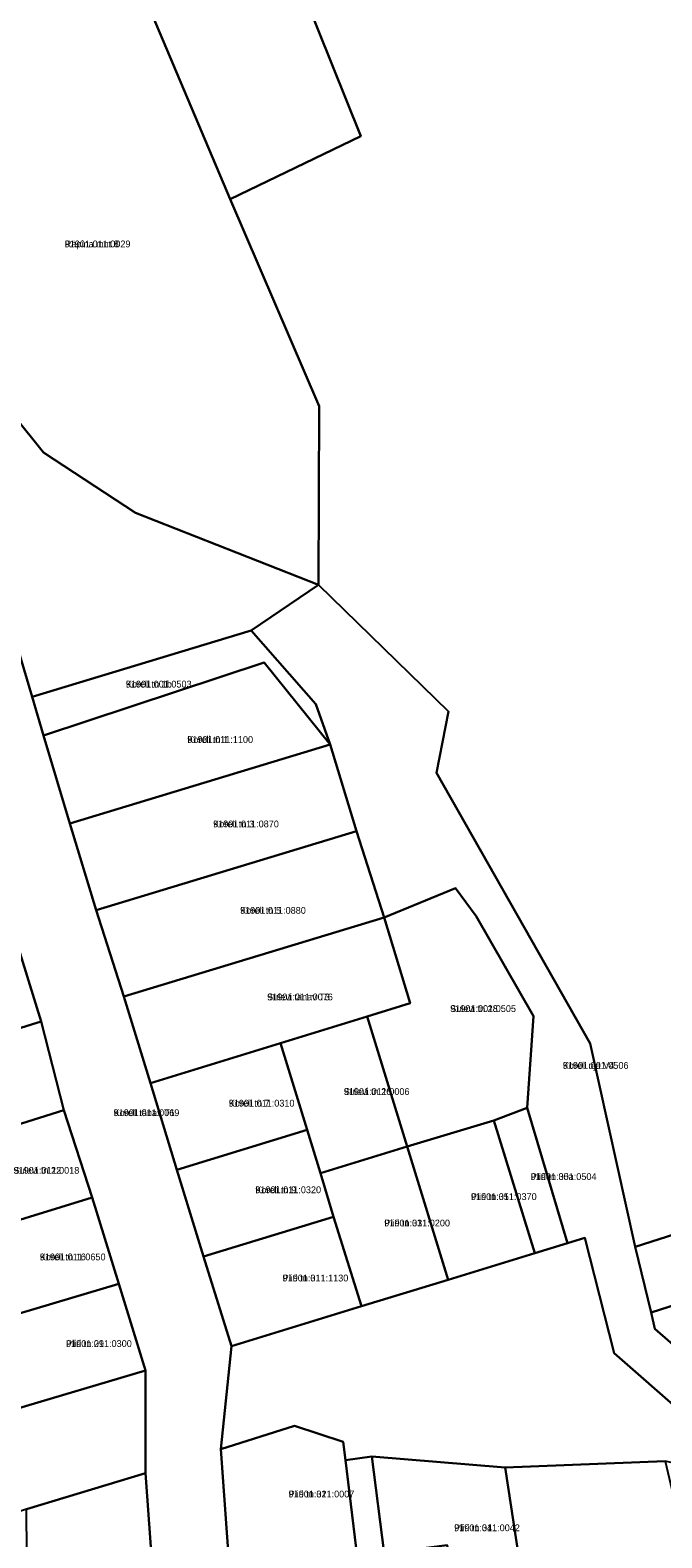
# Model space of a CAD drawing. Extents: x 675810 to 681273, y 6411190 to 6417565.
# Drawn here: x 678927.8 to 679067.1, y 6414897.2 to 6415229.9 of the extents above; entities that cross this region are included whole.
import ezdxf

# ---------------------------------------------------------------- set-up
doc = ezdxf.new("R2010")
doc.units = 0
for name, color, linetype in [('L_AADRESS', 7, 'Continuous'), ('PIIR', 7, 'Continuous'), ('TUNNUS', 7, 'Continuous')]:
    doc.layers.add(name, color=color, linetype=linetype)

msp = doc.modelspace()

# ---------------------------------------------------------------- linework, layer by layer
at = {"layer": 'PIIR'}
for points in [[(679238.99, 6415018.2), (679061.22, 6414961.43), (679051.32, 6415006.26), (679017.45, 6415066.02), (679020.06, 6415079.54), (678991.43, 6415107.45), (678991.54, 6415146.92), (678971.88, 6415192.56), (679000.73, 6415206.48), (678975.31, 6415269.85), (679026.21, 6415288.48), (679036.29, 6415260.94), (679042.8, 6415263.32), (679133.21, 6415296.47)], [(678907.99, 6415150.83), (678928.23, 6415082.74), (678930.76, 6415074.23), (678936.53, 6415054.84), (678942.34, 6415035.68), (678948.45, 6415016.65), (678954.32, 6414997.52), (678960.17, 6414978.4), (678966.04, 6414959.29), (678972.21, 6414939.48), (678969.88, 6414916.74), (678972, 6414887.15)], [(679072, 6414924.49), (679056.59, 6414937.95), (679050.17, 6414963.38), (679046.33, 6414962.2), (679037.43, 6414992.05), (679038.79, 6415012.34), (679026.19, 6415034.35), (679021.61, 6415040.53), (679005.86, 6415034.08), (678999.75, 6415053.14), (678993.95, 6415072.26), (678990.84, 6415081.16), (678976.51, 6415097.38), (678991.43, 6415107.45), (679020.06, 6415079.54), (679017.45, 6415066.02), (679051.32, 6415006.26), (679061.22, 6414961.43), (679064.74, 6414946.94), (679065.6, 6414943.33), (679076.56, 6414933.76)], [(678956.03, 6414872.89), (678953.21, 6414911.44), (678953.22, 6414934.12), (678947.33, 6414953.22), (678941.44, 6414972.33), (678935.25, 6414991.58), (678930.22, 6415011.1), (678924.33, 6415030.21)], [(679145.84, 6414896.58), (679067.84, 6414914.13), (679032.54, 6414912.69), (679003.18, 6414915.16), (678997.34, 6414914.37), (678996.85, 6414918.42), (678986.12, 6414921.92), (678969.88, 6414916.74), (678972.21, 6414939.48), (679000.89, 6414948.31), (679019.98, 6414954.16), (679039.1, 6414960.02), (679046.33, 6414962.2), (679050.17, 6414963.38), (679056.59, 6414937.95), (679072, 6414924.49), (679167.39, 6414906.13), (679297.57, 6414893.92), (679335.8, 6414897.92), (679339.92, 6414883.16)]]:
    msp.add_lwpolyline(points, dxfattribs=at)
for points in [[(678944.73, 6415258.64), (678975.31, 6415269.85), (679000.73, 6415206.48), (678971.88, 6415192.56), (678953.18, 6415237.02), (678947.08, 6415252.89)], [(678938.21, 6415256.44), (678940.28, 6415250.38), (678947.08, 6415252.89), (678953.18, 6415237.02), (678971.88, 6415192.56), (678991.54, 6415146.92), (678991.43, 6415107.45), (678951.01, 6415123.4), (678930.74, 6415136.65), (678883.06, 6415196.06), (678814.45, 6415217.97), (678811.5, 6415229.05), (678924.62, 6415251.82)], [(678811.5, 6415229.05), (678814.45, 6415217.97), (678883.06, 6415196.06), (678930.74, 6415136.65), (678951.01, 6415123.4), (678991.43, 6415107.45), (678976.51, 6415097.38), (678928.23, 6415082.74), (678907.99, 6415150.83), (678896.81, 6415163.44), (678866.24, 6415192.19), (678833.97, 6415200.67), (678806.69, 6415206.19), (678789.69, 6415215.27), (678785.99, 6415219.46), (678784.18, 6415224.88)], [(678930.76, 6415074.23), (678928.23, 6415082.74), (678976.51, 6415097.38), (678990.84, 6415081.16), (678993.95, 6415072.26), (678979.43, 6415090.36)], [(678936.53, 6415054.84), (678930.76, 6415074.23), (678979.43, 6415090.36), (678993.95, 6415072.26)], [(678999.75, 6415053.14), (678942.34, 6415035.68), (678936.53, 6415054.84), (678993.95, 6415072.26)], [(678999.75, 6415053.14), (679005.86, 6415034.08), (678948.45, 6415016.65), (678942.34, 6415035.68)], [(679005.86, 6415034.08), (679021.61, 6415040.53), (679026.19, 6415034.35), (679038.79, 6415012.34), (679037.43, 6414992.05), (679030.1, 6414989.29), (679010.94, 6414983.54), (679002.12, 6415012.21), (679011.6, 6415015.17)], [(678948.45, 6415016.65), (679005.86, 6415034.08), (679011.6, 6415015.17), (679002.12, 6415012.21), (678983, 6415006.33), (678954.32, 6414997.52)], [(678895.65, 6415021.37), (678924.33, 6415030.21), (678930.22, 6415011.1), (678901.53, 6415002.27)], [(679244.09, 6415004.39), (679064.74, 6414946.94), (679061.22, 6414961.43), (679238.99, 6415018.2)], [(678777.48, 6414963.9), (678805.96, 6414972.84), (678825.07, 6414978.72), (678844.19, 6414984.61), (678863.31, 6414990.49), (678882.46, 6414996.39), (678901.53, 6415002.27), (678930.22, 6415011.1), (678935.25, 6414991.58), (678906.93, 6414982.64), (678887.82, 6414976.76), (678868.7, 6414970.88), (678849.58, 6414965), (678830.47, 6414959.11), (678811.35, 6414953.21), (678782.68, 6414944.38)], [(679010.94, 6414983.54), (678991.83, 6414977.66), (678988.88, 6414987.22), (678983, 6415006.33), (679002.12, 6415012.21)], [(679076.56, 6414933.76), (679065.6, 6414943.33), (679064.74, 6414946.94), (679244.09, 6415004.39), (679255.75, 6415008.13), (679263.5, 6414986.2), (679272.89, 6414959.53), (679314.4, 6414967.13), (679333.36, 6414907.74), (679297.53, 6414903.93), (679168.83, 6414916.01)], [(678954.32, 6414997.52), (678983, 6415006.33), (678988.88, 6414987.22), (678960.17, 6414978.4)], [(678906.93, 6414982.64), (678935.25, 6414991.58), (678941.44, 6414972.33), (678912.78, 6414963.51)], [(679030.1, 6414989.29), (679037.43, 6414992.05), (679046.33, 6414962.2), (679039.1, 6414960.02)], [(679019.98, 6414954.16), (679010.94, 6414983.54), (679030.1, 6414989.29), (679039.1, 6414960.02)], [(678960.17, 6414978.4), (678988.88, 6414987.22), (678991.83, 6414977.66), (678994.73, 6414968.07), (678966.04, 6414959.29)], [(679000.89, 6414948.31), (678994.73, 6414968.07), (678991.83, 6414977.66), (679010.94, 6414983.54), (679019.98, 6414954.16)], [(678918.19, 6414944.55), (678915.25, 6414954.11), (678912.78, 6414963.51), (678941.44, 6414972.33), (678947.33, 6414953.22)], [(678966.04, 6414959.29), (678994.73, 6414968.07), (679000.89, 6414948.31), (678972.21, 6414939.48)], [(678918.19, 6414944.55), (678947.33, 6414953.22), (678953.22, 6414934.12), (678924.07, 6414925.43)], [(678800.31, 6414887.05), (678828.99, 6414895.88), (678848.11, 6414901.76), (678867.23, 6414907.65), (678886.34, 6414913.53), (678904.95, 6414919.55), (678924.07, 6414925.43), (678953.22, 6414934.12), (678953.21, 6414911.44), (678926.95, 6414903.55), (678879.9, 6414887.67), (678849.35, 6414877.97), (678801.1, 6414862.51)], [(678969.88, 6414916.74), (678986.12, 6414921.92), (678996.85, 6414918.42), (678997.34, 6414914.37), (678999.71, 6414894.92), (678972, 6414887.15)], [(678999.96, 6414893.03), (678999.71, 6414894.92), (678997.34, 6414914.37), (679003.18, 6414915.16), (679005.91, 6414893.79), (679019.8, 6414895.56), (679023.59, 6414865.82), (679003.75, 6414863.27)], [(679003.18, 6414915.16), (679032.54, 6414912.69), (679039.44, 6414867.83), (679023.59, 6414865.82), (679019.8, 6414895.56), (679005.91, 6414893.79)], [(678956.03, 6414872.89), (678927.3, 6414864.25), (678926.95, 6414903.55), (678953.21, 6414911.44)], [(679032.54, 6414912.69), (679067.84, 6414914.13), (679079.53, 6414864.4), (679073.48, 6414862.59), (679041.72, 6414853.06), (679039.44, 6414867.83)]]:
    msp.add_lwpolyline(points, close=True, dxfattribs=at)

# ---------------------------------------------------------------- texts
at = {"layer": 'L_AADRESS'}
for s, p in [('Räpina mnt 8', (678935.42, 6415181.95)), ('Koreli tn 1b', (678948.9, 6415084.82)), ('Koreli tn 1', (678962.46, 6415072.6)), ('Koreli tn 3', (678968.15, 6415053.97)), ('Koreli tn 5', (678974.1, 6415034.9)), ('Sulevi tänav T3', (678980.06, 6415015.8)), ('Sulevi tn 28', (679020.45, 6415013.23)), ('Koreli oja V4', (679045.28, 6415000.69)), ('Sulevi tn 26', (678996.97, 6414994.93)), ('Koreli tänav T1', (678946.2, 6414990.26)), ('Koreli tn 7', (678971.6, 6414992.36)), ('Sulevi tn 22', (678924.13, 6414977.54)), ('Koreli tn 9', (678977.46, 6414973.25)), ('Piiri tn 35a', (679038.21, 6414976.16)), ('Piiri tn 35', (679025.02, 6414971.74)), ('Piiri tn 33', (679005.9, 6414965.92)), ('Koreli tn 16', (678929.92, 6414958.44)), ('Piiri tn 31', (678983.47, 6414953.78)), ('Piiri tn 29', (678935.71, 6414939.32)), ('Piiri tn 32', (678984.8, 6414906.12)), ('Piiri tn 34', (679021.31, 6414898.67))]:
    msp.add_text(s, height=1.5, dxfattribs=at).set_placement(p)
at = {"layer": 'TUNNUS'}
for s, p in [('91901:011:0029', (678935.42, 6415181.95)), ('91901:001:0503', (678948.9, 6415084.82)), ('91901:011:1100', (678962.46, 6415072.6)), ('91901:011:0870', (678968.15, 6415053.97)), ('91901:011:0880', (678974.1, 6415034.9)), ('91901:011:0076', (678980.06, 6415015.8)), ('91901:001:0505', (679020.45, 6415013.23)), ('91901:001:0506', (679045.28, 6415000.69)), ('91901:011:0006', (678996.97, 6414994.93)), ('91901:011:0069', (678946.2, 6414990.26)), ('91901:011:0310', (678971.6, 6414992.36)), ('91901:011:0018', (678924.13, 6414977.54)), ('91901:011:0320', (678977.46, 6414973.25)), ('91901:001:0504', (679038.21, 6414976.16)), ('91901:011:0370', (679025.02, 6414971.74)), ('91901:011:0200', (679005.9, 6414965.92)), ('91901:011:0650', (678929.92, 6414958.44)), ('91901:011:1130', (678983.47, 6414953.78)), ('91901:011:0300', (678935.71, 6414939.32)), ('91901:011:0007', (678984.8, 6414906.12)), ('91901:011:0042', (679021.31, 6414898.67))]:
    msp.add_text(s, height=1.5, dxfattribs=at).set_placement(p)

doc.saveas('drawing.dxf')
